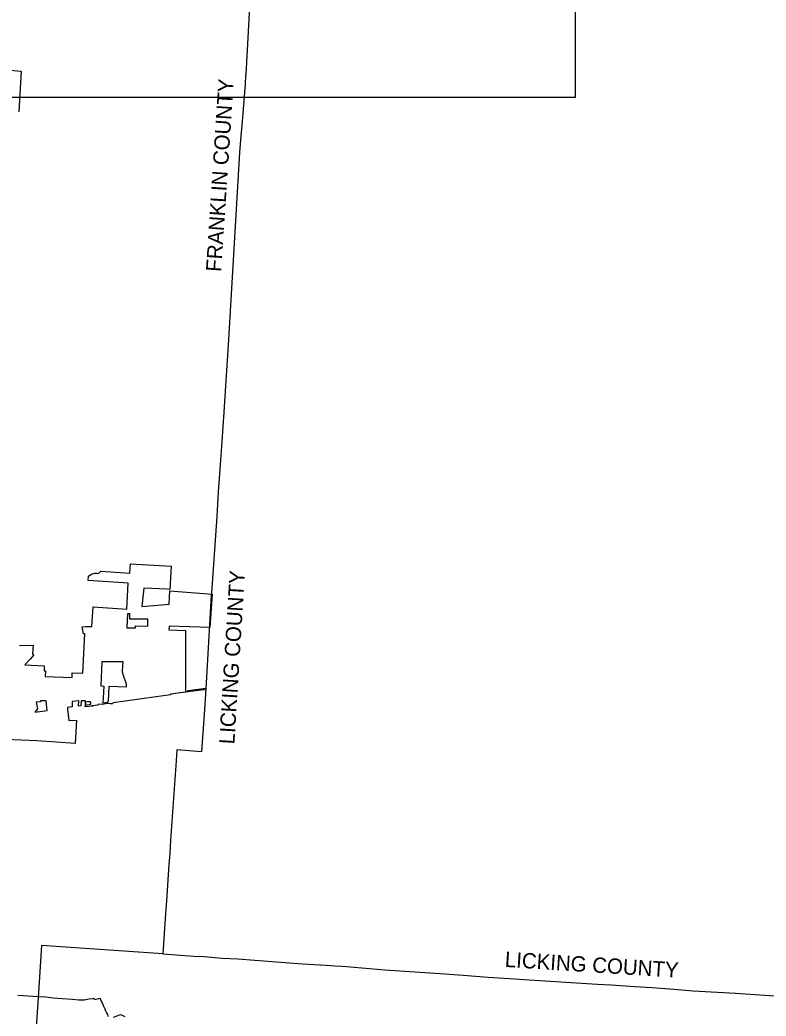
# Model space of a CAD drawing. Extents: x 1674899 to 2057726, y 653888 to 988278.
# Drawn here: x 1879943 to 1928708, y 702553 to 767682 of the extents above; entities that cross this region are included whole.
import ezdxf

# ---------------------------------------------------------------- set-up
doc = ezdxf.new("R2010")
doc.units = 0
for name, color, linetype in [('GM_X_Adjacent_County', 7, 'Continuous'), ('GM_X_Adjacent_County_Text', 7, 'Continuous'), ('GM_X_Corporation', 7, 'Continuous'), ('SH_Named_Boundary', 7, 'Continuous')]:
    doc.layers.add(name, color=color, linetype=linetype)

msp = doc.modelspace()

# ---------------------------------------------------------------- linework, layer by layer
at = {"layer": 'GM_X_Adjacent_County'}
for points in [[(1895161, 772565), (1894704, 764108), (1894692, 764059), (1894658, 763478), (1894436, 760788), (1894418, 760567), (1894359, 759837), (1894293, 759014), (1894201, 757542), (1893595, 747153), (1893596, 747130), (1893480, 745419), (1893416, 744442), (1893266, 742034), (1893131, 740129), (1893022, 738600), (1892908, 736832), (1892812, 735226), (1892456, 730219), (1892450, 730067), (1892092, 723948), (1892003, 722602), (1891818, 719820), (1890201, 719965), (1890151, 719240), (1889790, 714054), (1889730, 713187), (1889680, 712466), (1889514, 710092), (1889457, 709269), (1889273, 706617), (1886742, 706790), (1881354, 707158), (1881125, 703749), (1880996, 701827)], [(1895161, 772565), (1894704, 764108), (1894692, 764059), (1894658, 763478), (1894436, 760788), (1894418, 760567), (1894359, 759837), (1894293, 759014), (1894201, 757542), (1893595, 747153), (1893596, 747130), (1893480, 745419), (1893416, 744442), (1893266, 742034), (1893131, 740129), (1893022, 738600), (1892908, 736832), (1892812, 735226), (1892456, 730219), (1892450, 730067), (1892092, 723948), (1892003, 722602), (1891818, 719820), (1890201, 719965), (1890151, 719240), (1889790, 714054), (1889730, 713187), (1889680, 712466), (1889514, 710092), (1889457, 709269), (1889273, 706617), (1891303, 706473), (1891975, 706450), (1893167, 706341), (1894181, 706293), (1895291, 706208), (1898404, 705970), (1899948, 705886), (1900525, 705845), (1900989, 705810), (1901286, 705791), (1903789, 705582), (1907402, 705335), (1908911, 705219), (1910549, 705095), (1912289, 704987), (1913214, 704928), (1917684, 704645), (1918576, 704593), (1920103, 704495), (1921268, 704418), (1922415, 704341), (1923944, 704214), (1926704, 704049), (1932110, 703691)]]:
    msp.add_lwpolyline(points, dxfattribs=at)
at = {"layer": 'GM_X_Corporation'}
for points in [[(1879037, 764411), (1880021, 764338), (1879881, 761666)], [(1879904, 726784), (1880802, 726800), (1880768, 726227), (1880859, 726175), (1880608, 725893), (1880265, 725517), (1881530, 725461), (1881516, 725121), (1881606, 725118), (1881592, 724760), (1883349, 724690), (1883361, 724998), (1884063, 724970), (1884189, 727538), (1884093, 727538), (1884018, 728000), (1884248, 728032), (1884634, 728017), (1884730, 729301), (1886931, 729158), (1887026, 730859), (1884407, 731040), (1884418, 731332), (1884454, 731340), (1884555, 731405), (1884625, 731441), (1884838, 731506), (1884894, 731518), (1884944, 731507), (1885008, 731495), (1885091, 731518), (1885210, 731612), (1885226, 731646), (1887123, 731518), (1887171, 732116), (1889833, 731961), (1889750, 730440), (1889536, 730456), (1888047, 730541), (1887910, 729337), (1889698, 729488), (1889745, 730351), (1892496, 730147), (1892357, 727950), (1889689, 728043), (1889673, 727801), (1890758, 727769), (1890758, 723783), (1890911, 723805), (1890916, 723842), (1892095, 723998), (1892087, 723879), (1891935, 723861), (1891934, 723876), (1889794, 723593), (1889793, 723554), (1886658, 723112), (1886027, 723024), (1885970, 722976), (1885862, 722961), (1885816, 722993), (1885568, 722959), (1885561, 722973), (1885296, 722935), (1885291, 722955), (1885033, 722919), (1885033, 722885), (1884694, 722835), (1884698, 722806), (1884659, 722802), (1884661, 722831), (1884459, 722802), (1884211, 722767), (1884219, 722882), (1884224, 723161), (1883939, 723154), (1883919, 722840), (1883781, 722820), (1883762, 722837), (1883783, 723164), (1883351, 723123), (1883349, 722765), (1883041, 722719), (1883051, 722628), (1883137, 721887), (1883642, 721894), (1883562, 720375), (1881059, 720539), (1877939, 720690)], [(1879804, 703931), (1881129, 703836), (1881141, 703834), (1881613, 703801), (1882113, 703751), (1882706, 703704), (1883370, 703649), (1883784, 703623), (1884168, 703626), (1884454, 703676), (1884697, 703708), (1884772, 703725), (1884794, 703642), (1885113, 703708), (1885185, 703717), (1885188, 703702), (1885215, 703615), (1885243, 703546), (1885273, 703482), (1885332, 703365), (1885386, 703236), (1885482, 703024), (1885538, 702906), (1885604, 702757), (1885657, 702646), (1885696, 702574), (1885742, 702530)], [(1886052, 702483), (1886301, 702566), (1886505, 702653), (1886798, 702522)]]:
    msp.add_lwpolyline(points, dxfattribs=at)
for points in [[(1886922, 727930), (1887492, 727926), (1887501, 728061), (1888305, 728054), (1888305, 728496), (1887134, 728505), (1887134, 728853), (1886974, 728856)], [(1885391, 723357), (1885361, 723053), (1885362, 723028), (1885677, 723076), (1885680, 723113), (1885741, 723121), (1885781, 724128), (1886908, 724083), (1886910, 724172), (1886901, 724247), (1886709, 724830), (1886643, 725046), (1886648, 725104), (1886692, 725711), (1885289, 725711), (1885226, 724138), (1885430, 724123)], [(1881013, 723079), (1881081, 722639), (1880912, 722422), (1881719, 722535), (1881652, 723173), (1881277, 723155), (1881280, 723091)], [(1884221, 722891), (1884582, 722943), (1884582, 723076), (1884468, 723084), (1884469, 723116), (1884223, 723083)]]:
    msp.add_lwpolyline(points, close=True, dxfattribs=at)
at = {"layer": 'SH_Named_Boundary'}
msp.add_lwpolyline([(1741253, 762626), (1916253, 762626), (1916253, 897626), (1741253, 897626)], close=True, dxfattribs=at)

# ---------------------------------------------------------------- texts
at = {"layer": 'GM_X_Adjacent_County_Text'}
for s, rotation, p in [('FRANKLIN COUNTY', 86.22742, (1893094, 751191)), ('LICKING COUNTY', 86.4782, (1893956, 720303)), ('LICKING COUNTY', 356.39809, (1911611, 705771))]:
    msp.add_text(s, height=1000, rotation=rotation, dxfattribs=at).set_placement(p)

doc.saveas('drawing.dxf')
